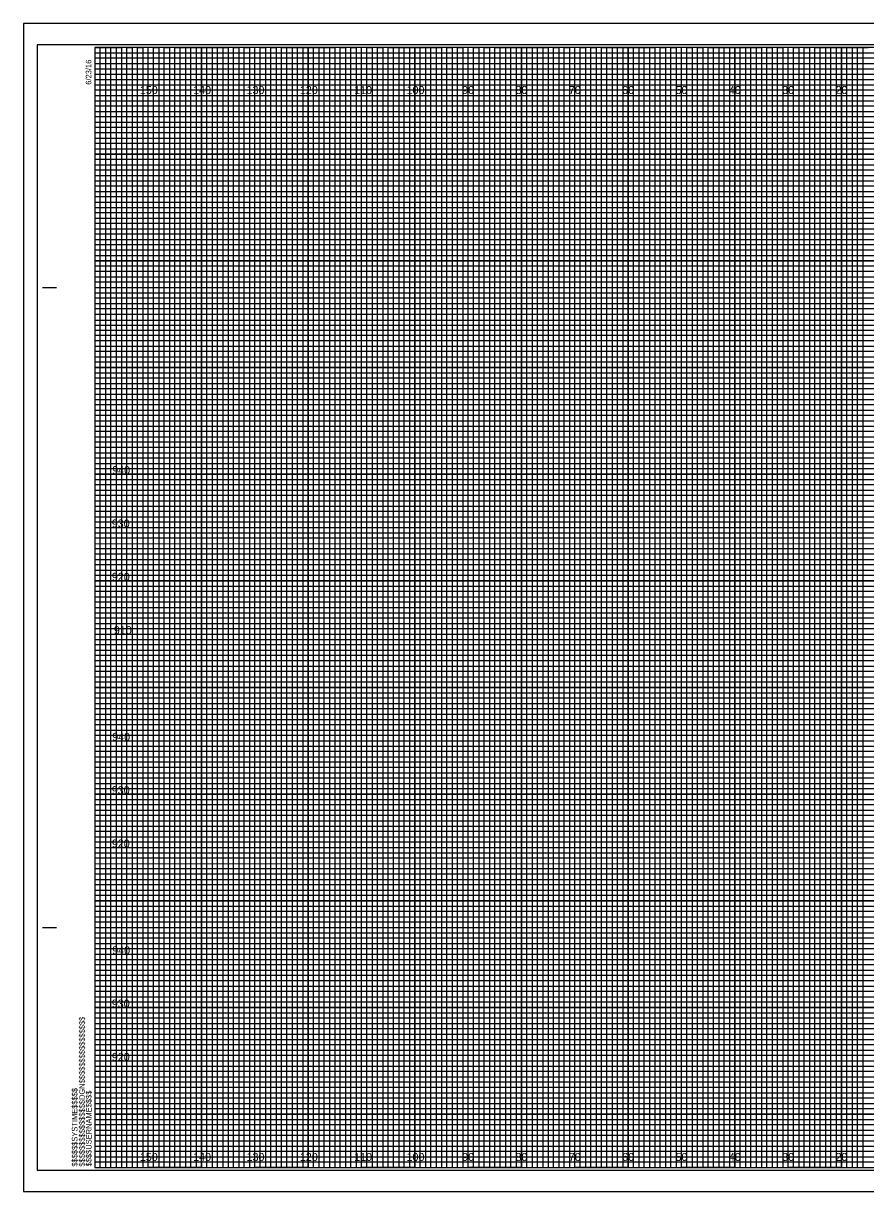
# Model space of a CAD drawing. Extents: x -13 to 323, y -4 to 214.
# Drawn here: x -13.4 to 144.5, y -4.5 to 214.5 of the extents above; entities that cross this region are included whole.
import ezdxf

# ---------------------------------------------------------------- set-up
doc = ezdxf.new("R2010")
doc.units = 0
for name, color, linetype in [('Prop XS Elevation Labels', 7, 'Continuous'), ('Prop XS Offset Labels', 7, 'Continuous'), ('Sheet Cross Section CELL', 7, 'Continuous'), ('Sheet Cross Section Grid Major CELL', 7, 'Continuous'), ('Sheet Cross Section Grid Middle CELL', 7, 'Continuous'), ('Sheet Cross Section Grid Minor 1 CELL', 7, 'Continuous'), ('Sheet Cross Section Grid Minor 2 CELL', 7, 'Continuous'), ('Sheet Cutting Line CELL', 7, 'Continuous'), ('Sheet DOT Grid CELL', 7, 'Continuous'), ('Sheet Plot Border Inside CELL', 7, 'Continuous'), ('Sheet Plot Border Outside CELL', 7, 'Continuous')]:
    doc.layers.add(name, color=color, linetype=linetype)

msp = doc.modelspace()

# ---------------------------------------------------------------- linework, layer by layer
at = {"layer": 'Sheet Cross Section CELL'}
for p, q in [((-9.8, 165), (-7.3, 165)), ((-9.7, 165), (-7.2, 165)), ((-9.8, 45), (-7.3, 45)), ((-9.7, 45), (-7.2, 45)), ((0, 0), (0, 0)), ((0, 0), (0, 0)), ((0, 0), (0, 0)), ((0, 0), (0, 0)), ((0, 0), (0, 0)), ((0, 0), (0, 0)), ((0, 0), (0, 0))]:
    msp.add_line(p, q, dxfattribs=at)
msp.add_lwpolyline([(320, 210), (0, 210), (0, 0), (320, 0)], close=True, dxfattribs=at)
at = {"layer": 'Sheet Cross Section Grid Major CELL'}
for p, q in [((10, 210), (0, 210)), ((10, 0), (10, 210)), ((30, 210), (20, 210)), ((20, 210), (20, 0)), ((30, 0), (30, 210)), ((50, 210), (40, 210)), ((40, 210), (40, 0)), ((50, 0), (50, 210)), ((70, 210), (60, 210)), ((60, 210), (60, 0)), ((70, 0), (70, 210)), ((90, 210), (80, 210)), ((80, 210), (80, 0)), ((90, 0), (90, 210)), ((110, 210), (100, 210)), ((100, 210), (100, 0)), ((110, 0), (110, 210)), ((130, 210), (120, 210)), ((120, 210), (120, 0)), ((130, 0), (130, 210)), ((150, 210), (140, 210)), ((140, 210), (140, 0)), ((20, 0), (10, 0)), ((40, 0), (30, 0)), ((60, 0), (50, 0)), ((80, 0), (70, 0)), ((100, 0), (90, 0)), ((120, 0), (110, 0)), ((140, 0), (130, 0))]:
    msp.add_line(p, q, dxfattribs=at)
for points in [[(0, 200), (320, 200), (320, 190), (0, 190)], [(0, 180), (320, 180), (320, 170), (0, 170)], [(0, 160), (320, 160), (320, 150), (0, 150)], [(0, 140), (320, 140), (320, 130), (0, 130)], [(0, 120), (320, 120), (320, 110), (0, 110)], [(0, 100), (320, 100), (320, 90), (0, 90)], [(0, 80), (320, 80), (320, 70), (0, 70)], [(0, 60), (320, 60), (320, 50), (0, 50)], [(0, 40), (320, 40), (320, 30), (0, 30)], [(0, 20), (320, 20), (320, 10), (0, 10)]]:
    msp.add_lwpolyline(points, dxfattribs=at)
at = {"layer": 'Sheet Cross Section Grid Middle CELL'}
for points in [[(0, 210), (5, 210), (5, 0), (15, 0), (15, 210), (25, 210), (25, 0), (35, 0), (35, 210), (45, 210), (45, 0), (55, 0), (55, 210), (65, 210), (65, 0), (75, 0), (75, 210), (85, 210), (85, 0), (95, 0), (95, 210), (105, 210), (105, 0), (115, 0), (115, 210), (125, 210), (125, 0), (135, 0), (135, 210), (145, 210)], [(0, 205), (275, 205)], [(0, 185), (320, 185), (320, 195), (0, 195)], [(0, 165), (320, 165), (320, 175), (0, 175)], [(0, 145), (320, 145), (320, 155), (0, 155)], [(0, 125), (320, 125), (320, 135), (0, 135)], [(0, 105), (320, 105), (320, 115), (0, 115)], [(0, 85), (320, 85), (320, 95), (0, 95)], [(0, 65), (320, 65), (320, 75), (0, 75)], [(0, 45), (320, 45), (320, 55), (0, 55)], [(0, 25), (320, 25), (320, 35), (0, 35)], [(0, 5), (320, 5), (320, 15), (0, 15)]]:
    msp.add_lwpolyline(points, dxfattribs=at)
at = {"layer": 'Sheet Cross Section Grid Minor 1 CELL'}
for p, q in [((0, 209), (260, 209)), ((260, 207.98), (0, 207.98)), ((0, 207.98), (0, 207)), ((0, 207), (260, 207)), ((260, 205.89), (0, 205.89)), ((0, 205.89), (0, 204)), ((0, 204), (320, 204))]:
    msp.add_line(p, q, dxfattribs=at)
for points in [[(0, 203), (270, 203), (320, 203), (320, 202), (0, 202)], [(0, 201), (320, 201), (320, 199), (0, 199)], [(0, 198), (320, 198), (320, 197), (0, 196.98)], [(0, 196), (320, 196), (320, 194), (0, 194)], [(0, 193), (320, 193), (320, 192), (0, 192)], [(0, 191), (320, 191), (320, 189), (0, 189)], [(0, 188), (320, 188), (320, 187), (0, 187)], [(0, 186), (320, 186), (320, 184), (0, 184)], [(0, 183), (320, 183), (320, 182), (0, 182)], [(0, 181), (320, 181), (320, 179), (0, 179)], [(0, 178), (320, 178), (320, 177), (0, 177)], [(0, 176), (320, 176), (320, 173.95), (320, 173), (320, 172), (0, 172)], [(0, 174), (320, 174), (320, 173), (0, 173)], [(0, 171), (320, 171), (320, 169), (0, 169.03)], [(0, 169.03), (320, 169), (320, 168), (0, 168)], [(0, 167), (320, 167), (320, 166), (0, 166)], [(0, 164), (320, 164), (320, 163), (0, 163)], [(0, 162), (320, 162), (320, 161), (0, 161)], [(-0.07, 158.89), (320, 158.89), (320, 157.88), (-0.07, 157.88)], [(0, 157), (320, 157), (320, 156), (0, 156)], [(0, 154), (320, 154), (320, 153), (0, 153)], [(0, 152), (320, 152), (320, 151), (0, 151)], [(0, 149), (320, 149), (320, 148), (0, 148)], [(0, 147), (320, 147), (320, 146), (0, 146)], [(0, 144), (320, 144), (320, 143), (0, 143)], [(0, 142), (320, 142), (320, 141), (0, 141)], [(0, 139), (320, 139), (319.99, 137.98), (0, 138)], [(0, 137), (320, 137), (320, 136), (0, 136)], [(0, 134), (320, 134), (320, 133), (0, 133)], [(0, 132), (320, 132), (320, 131), (0, 131)], [(0, 129), (320, 129), (320, 128), (0, 128)], [(0, 127), (320, 127), (320, 126), (0, 126)], [(0, 124), (320, 124), (320, 123), (0, 123)], [(0, 122), (320, 122), (320, 121), (0, 121)], [(0, 119), (320, 119), (320, 118), (0, 118)], [(0, 116.99), (320.07, 116.91), (320, 116), (0, 116)], [(0, 114), (320, 114), (320, 113), (0, 113)], [(0, 112), (320, 112), (320, 111), (0, 111)], [(0, 109), (320, 109), (320, 108), (0, 108)], [(0, 107), (320, 107), (320, 106), (0, 106)], [(0, 104), (320, 104), (320, 103), (0, 103)], [(0, 102), (320, 102), (320, 101), (0, 101)], [(0, 99), (320, 99), (320, 98), (0, 98)], [(0, 97), (320, 97), (320, 96), (0, 96)], [(0, 94), (320, 94), (320, 93), (0, 93)], [(0, 92), (320, 92), (320, 91), (0, 91)], [(0, 89), (320, 89), (320, 88), (0, 88)], [(0, 87), (320, 87), (320, 86), (0, 86)], [(0, 84), (320, 84), (320, 83), (0, 83)], [(0, 82), (320, 82), (320, 81), (0, 81)], [(0, 79), (320, 79), (319.99, 77.98), (0, 78)], [(0, 77), (320, 77), (320, 76), (0, 76)], [(0, 74), (320, 74), (320, 73), (0, 73)], [(0, 72), (320, 72), (320, 71), (0, 71)], [(0, 69), (320, 69), (320, 68), (0, 68)], [(0, 67), (320, 67), (320, 66), (0, 66)], [(0, 64), (320, 64), (320, 63), (0, 63)], [(0, 62), (320, 62), (320, 61), (0, 61)], [(0, 59), (320, 59), (320, 58), (0, 58)], [(0, 56.99), (320.07, 56.91), (320, 56), (0, 56)], [(0, 54), (320, 54), (320, 53), (0, 53)], [(0, 52), (320, 52), (320, 51), (0, 51)], [(0, 49), (320, 49), (320, 48), (0, 48)], [(0, 47), (320, 47), (320, 46), (0, 46)], [(0, 44), (320, 44), (320, 43), (0, 43)], [(0, 42), (320, 42), (320, 41), (0, 41)], [(0, 39), (320, 39), (320, 38), (0, 38)], [(0, 37), (320, 37), (320, 36), (0, 36)], [(0, 34), (320, 34), (320, 33), (0, 33)], [(0, 32), (320, 32), (320, 31), (0, 31)], [(0, 29), (320, 29), (320, 28), (0, 28)], [(0, 27), (320, 27), (320, 26), (0, 26)], [(0, 24), (320, 24), (320, 23), (0, 23)], [(0, 22), (320, 22), (320, 21), (0, 21)], [(0, 19), (320, 19), (320, 18), (0, 18)], [(0, 17), (320, 17), (320, 16), (0, 16)], [(0, 14), (320, 14), (320, 13), (0, 13)], [(0, 12), (320, 12), (320, 11), (0, 11)], [(0, 9), (320, 9), (320, 8), (0, 8)], [(0, 7), (320, 7), (320, 6), (0, 6)], [(0, 4), (320, 4), (320, 3), (0, 3)], [(0, 2), (320, 2), (320, 1), (0, 1)]]:
    msp.add_lwpolyline(points, dxfattribs=at)
at = {"layer": 'Sheet Cross Section Grid Minor 2 CELL'}
for points in [[(0, 0), (1, 0), (1, 210), (2, 210), (2, 0)], [(2, 0), (3, 0), (3, 210), (4, 210), (4, 0)], [(5, 0), (6, 0), (6, 210), (7, 210), (7, 0)], [(7, 0), (8, 0), (8, 210), (9, 210), (9, 0)], [(10, 0), (11, 0), (11, 210), (12, 210), (12, 0)], [(12, 0), (13, 0), (13, 210), (14, 210), (14, 0)], [(15, 0), (16, 0), (16, 210), (17, 210), (17, 0)], [(17, 0), (18, 0), (18, 210), (19, 210), (19, 0)], [(20, 0), (21, 0), (21, 210), (22, 210), (22, 0)], [(22, 0), (23, 0), (23, 210), (24, 210), (24, 0)], [(25, 0), (26, 0), (26, 210), (27, 210), (27, 0)], [(27, 0), (28, 0), (28, 210), (29, 210), (29, 0)], [(30, 0), (31, 0), (31, 210), (32, 210), (32, 0)], [(32, 0), (33, 0), (33, 210), (34, 210), (34, 0)], [(35, 0), (36, 0), (36, 210), (37, 210), (37, 0)], [(37, 0), (38, 0), (38, 210), (39, 210), (39, 0)], [(40, 0), (41, 0), (41, 210), (42, 210), (42, 0)], [(42, 0), (43, 0), (43, 210), (44, 210), (44, 0)], [(45, 0), (46, 0), (46, 210), (47, 210), (47, 0)], [(47, 0), (48, 0), (48, 210), (49, 210), (49, 0)], [(50, 0), (51, 0), (51, 210), (52, 210), (52, 0)], [(52, 0), (53, 0), (53, 210), (54, 210), (54, 0)], [(55, 0), (56, 0), (56, 210), (57, 210), (57, 0)], [(57, 0), (58, 0), (58, 210), (59, 210), (59, 0)], [(60, 0), (61, 0), (61, 210), (62, 210), (62, 0)], [(62, 0), (63, 0), (63, 210), (64, 210), (64, 0)], [(65, 0), (66, 0), (66, 210), (67, 210), (67, 0)], [(67, 0), (68, 0), (68, 210), (69, 210), (69, 0)], [(70, 0), (71, 0), (71, 210), (72, 210), (72, 0)], [(72, 0), (73, 0), (73, 210), (74, 210), (74, 0)], [(75, 0), (76, 0), (76, 210), (77, 210), (77, 0)], [(77, 0), (78, 0), (78, 210), (79, 210), (79, 0)], [(80, 0), (81, 0), (81, 210), (82, 210), (82, 0)], [(82, 0), (83, 0), (83, 210), (84, 210), (84, 0)], [(85, 0), (86, 0), (86, 210), (87, 210), (87, 0)], [(87, 0), (88, 0), (88, 210), (89, 210), (89, 0)], [(90, 0), (91, 0), (91, 210), (92, 210), (92, 0)], [(92, 0), (93, 0), (93, 210), (94, 210), (94, 0)], [(95, 0), (96, 0), (96, 210), (97, 210), (97, 0)], [(97, 0), (98, 0), (98, 210), (99, 210), (99, 0)], [(100, 0), (101, 0), (101, 210), (102, 210), (102, 0)], [(102, 0), (103, 0), (103, 210), (104, 210), (104, 0)], [(105, 0), (106, 0), (106, 210), (107, 210), (107, 0)], [(107, 0), (108, 0), (108, 210), (109, 210), (109, 0)], [(110, 0), (111, 0), (111, 210), (112, 210), (112, 0)], [(112, 0), (113, 0), (113, 210), (114, 210), (114, 0)], [(115, 0), (116, 0), (116, 210), (117, 210), (117, 0)], [(117, 0), (118, 0), (118, 210), (119, 210), (119, 0)], [(120, 0), (121, 0), (121, 210), (122, 210), (122, 0)], [(122, 0), (123, 0), (123, 210), (124, 210), (124, 0)], [(125, 0), (126, 0), (126, 210), (127, 210), (127, 0)], [(127, 0), (128, 0), (128, 210), (129, 210), (129, 0)], [(130, 0), (131, 0), (131, 210), (132, 210), (132, 0)], [(132, 0), (133, 0), (133, 210), (134, 210), (134, 0)], [(135, 0), (136, 0), (136, 210), (137, 210), (137, 0)], [(137, 0), (138, 0), (138, 210), (139, 210), (139, 0)], [(140, 0), (141, 0), (141, 210), (142, 210), (142, 0)], [(142, 0), (143, 0), (143, 210), (144, 210), (144, 0)]]:
    msp.add_lwpolyline(points, dxfattribs=at)
at = {"layer": 'Sheet Cutting Line CELL'}
for p, q in [((323.3, 214.5), (-13.4, 214.5)), ((-13.4, 214.5), (-13.4, -4.5)), ((-13.4, -4.5), (323.3, -4.5))]:
    msp.add_line(p, q, dxfattribs=at)
at = {"layer": 'Sheet DOT Grid CELL'}
for p, q in [((10, 0), (10, 210)), ((20, 0), (20, 210)), ((30, 0), (30, 210)), ((40, 0), (40, 210)), ((50, 0), (50, 210)), ((60, 0), (60, 210)), ((70, 0), (70, 210)), ((80, 0), (80, 210)), ((90, 0), (90, 210)), ((100, 0), (100, 210)), ((110, 0), (110, 210)), ((120, 0), (120, 210)), ((130, 0), (130, 210)), ((140, 0), (140, 210)), ((0, 200), (320, 200)), ((0, 190), (320, 190)), ((0, 180), (320, 180)), ((0, 170), (320, 170)), ((0, 160), (320, 160)), ((0, 150), (320, 150)), ((0, 140), (320, 140)), ((0, 130), (320, 130)), ((0, 120), (320, 120)), ((0, 110), (320, 110)), ((0, 100), (320, 100)), ((0, 90), (320, 90)), ((0, 80), (320, 80)), ((0, 70), (320, 70)), ((0, 60), (320, 60)), ((0, 50), (320, 50)), ((0, 40), (320, 40)), ((0, 30), (320, 30)), ((0, 20), (320, 20)), ((0, 10), (320, 10))]:
    msp.add_line(p, q, dxfattribs=at)
at = {"layer": 'Sheet Plot Border Inside CELL'}
msp.add_lwpolyline([(-10.8, -0.5), (322.4, -0.5), (322.4, 210.5), (-10.8, 210.5)], close=True, dxfattribs=at)
at = {"layer": 'Sheet Plot Border Outside CELL'}
msp.add_lwpolyline([(-13.4, -4.5), (323.3, -4.5), (323.3, 214.5), (-13.4, 214.5)], close=True, dxfattribs=at)

# ---------------------------------------------------------------- texts
at = {"layer": 'Prop XS Elevation Labels'}
for s, p in [('940', (3.26, 130)), ('930', (3.18, 120)), ('920', (3.19, 110)), ('910', (3.57, 100)), ('940', (3.26, 80)), ('930', (3.18, 70)), ('920', (3.19, 60)), ('940', (3.26, 40)), ('930', (3.18, 30)), ('920', (3.19, 20))]:
    msp.add_text(s, height=1.5, dxfattribs=at).set_placement(p)
at = {"layer": 'Prop XS Offset Labels'}
for s, p in [('150', (8.44, 201.25)), ('140', (18.44, 201.25)), ('130', (28.44, 201.25)), ('120', (38.44, 201.25)), ('110', (48.62, 201.25)), ('100', (58.44, 201.25)), ('90', (68.86, 201.25)), ('80', (78.86, 201.25)), ('70', (88.86, 201.25)), ('60', (98.86, 201.25)), ('50', (108.86, 201.25)), ('40', (118.86, 201.25)), ('30', (128.86, 201.25)), ('20', (138.86, 201.25)), ('150', (8.44, 1.25)), ('140', (18.44, 1.25)), ('130', (28.44, 1.25)), ('120', (38.44, 1.25)), ('110', (48.62, 1.25)), ('100', (58.44, 1.25)), ('90', (68.86, 1.25)), ('80', (78.86, 1.25)), ('70', (88.86, 1.25)), ('60', (98.86, 1.25)), ('50', (108.86, 1.25)), ('40', (118.86, 1.25)), ('30', (128.86, 1.25)), ('20', (138.86, 1.25))]:
    msp.add_text(s, height=1.5, dxfattribs=at).set_placement(p)
at = {"layer": 'Sheet Cross Section CELL'}
for s, p in [('6/23/16', (-0.65, 203)), ('$$$$$$$$$$$$$$$$DGN$$$$$$$$$$$$$$$$', (-1.88, 0.18)), ('$$$$$$SYSTIME$$$$$', (-3.26, 0.18)), ('$$$$USERNAME$$$$', (-0.62, 0.23))]:
    msp.add_text(s, height=1.05, rotation=90, dxfattribs=at).set_placement(p)

doc.saveas('drawing.dxf')
